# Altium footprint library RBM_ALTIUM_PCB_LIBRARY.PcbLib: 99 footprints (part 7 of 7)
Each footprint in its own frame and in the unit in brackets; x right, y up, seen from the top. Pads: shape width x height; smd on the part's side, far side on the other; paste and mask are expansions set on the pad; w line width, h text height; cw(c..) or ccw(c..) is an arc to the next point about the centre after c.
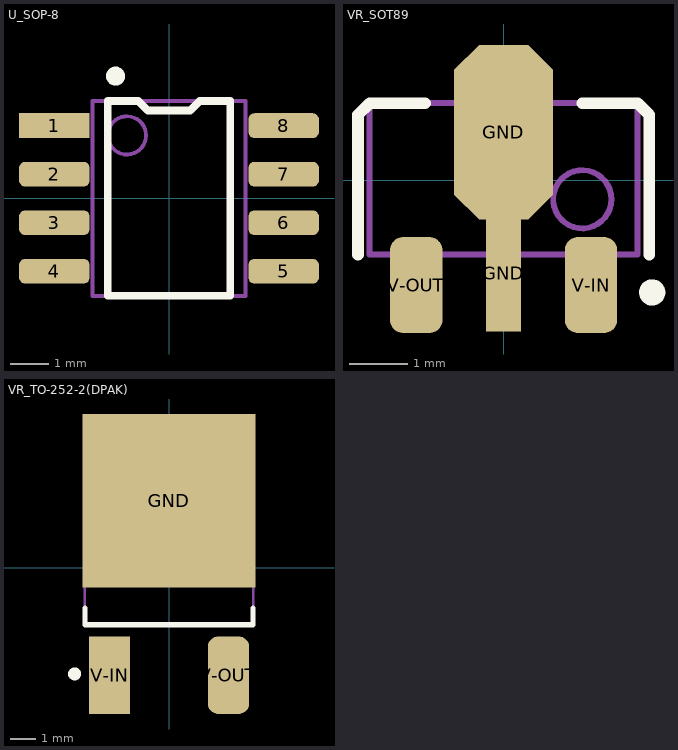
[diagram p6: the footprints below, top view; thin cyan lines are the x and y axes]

## U_SOP-8 [mm] "OB2225M"
height 1.75
pads (8):
  rect 1.85x0.65 smd mask+0.4: 1(-3,1.905)
  rrect50% 1.85x0.65 smd mask+0.4: 2(-3,0.635) 3(-3,-0.635) 4(-3,-1.905) 5(3,-1.905) 6(3,-0.635) 7(3,0.635) 8(3,1.905)
Top Overlay:
  circle w0.25: c-1.4,3.2 r0.125
  lines w0.2: -1.6,-2.55 -1.6,2.55 -0.8,2.55 -0.55,2.3 0.55,2.3 0.8,2.55 1.6,2.55 1.6,-2.55 -1.6,-2.55
Assembly Top:
  circle w0.1: c-1.1,1.65 r0.5
  lines w0.1: -2,-2.55 -2,2.55 2,2.55 2,-2.55 -2,-2.55
3D body "SOP127P600X175_HS-9N.step": height 1.75, standoff 0, extent -3,-2.55 3,2.55

## VR_SOT89 [mm] "SOT89, 3-Leads, Body 4.50x2.45mm, Pitch 1.50mm, Lead Span 4.1mm - Reverse Pinning, IPC Medium Density"
height 1.6
pads (4):
  rect 0.6x2 smd: GND(0,-1.6)
  oct 1.7x3 smd: GND(0,0.823)
  rrect50% 0.9x1.65 smd: V-IN(1.5,-1.8) V-OUT(-1.5,-1.8)
Top Overlay:
  circle w0.25: c2.55,-1.927 r0.1
  lines w0.2: -2.5,-1.277 -2.5,1.123 -2.3,1.323 -1.35,1.323 ; 1.35,1.323 2.3,1.323 2.5,1.123 2.5,-1.277
Mechanical 13:
  circle w0.1: c1.35,-0.327 r0.5
  lines w0.1: -2.3,-1.277 2.3,-1.277 2.3,1.323 -2.3,1.323 -2.3,-1.277
3D body "SOT89R-150P410X160-3N.step": height 1.6, standoff 0, extent -2.3,-2.2 2.3,1.8

## VR_TO-252-2(DPAK) [mm] "D-PAK, 3-Pads, Body 6.20x6.61mm (max), IPC Medium Density"
height 2.4
pads (3):
  rect 6.7x6.7 smd: GND(0,2.6)
  rect 1.6x3 smd: V-IN(-2.3,-4.15)
  rrect50% 1.6x3 smd: V-OUT(2.3,-4.15)
Top Overlay:
  circle w0.25: c-3.65,-4.1 r0.125
  lines w0.2: -3.25,-1.55 -3.25,-2.2 3.25,-2.2 3.25,-1.55
Mechanical 13:
  lines w0.1: -3.25,-2.2 3.25,-2.2 3.25,4 -3.25,4 -3.25,-2.2
3D body "ST7805.step": height 2.5, standoff 0, extent -3.25,-4.275 3.25,5.45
